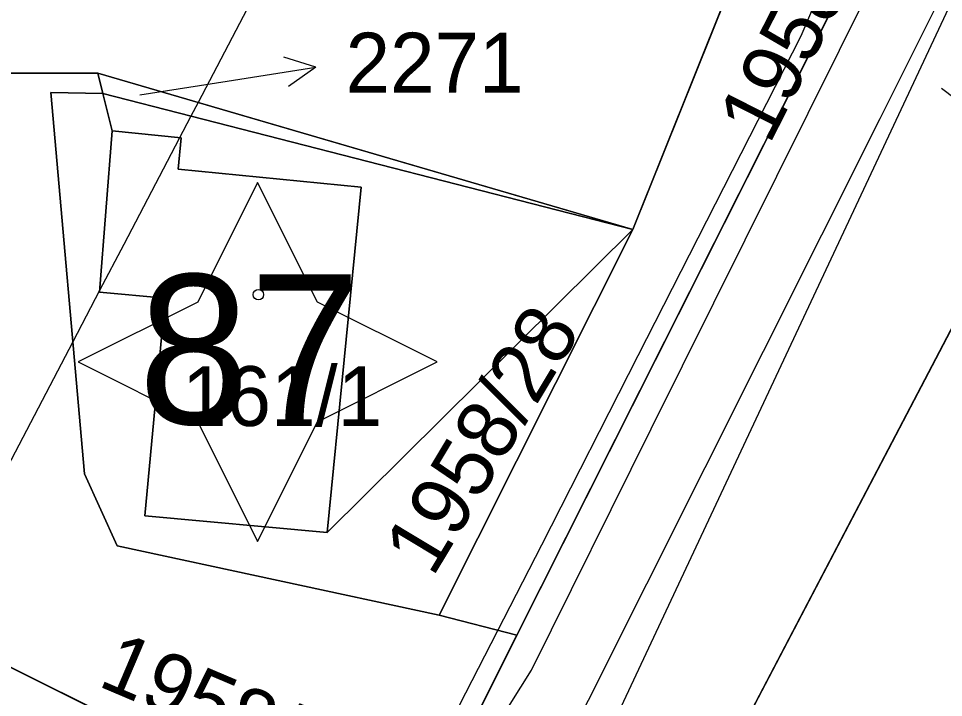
# Model space of a CAD drawing. Extents: x -706130 to -698555, y -971544 to -967260.
# Drawn here: x -704369.6 to -704338.67, y -970237.74 to -970215.04 of the extents above; entities that cross this region are included whole.
import ezdxf

# ---------------------------------------------------------------- set-up
doc = ezdxf.new("R2010")
doc.units = 0
for name, color, linetype in [('Architektonicky cenná stavba S', 7, 'Continuous'), ('BPEJ hranice S', 7, 'Continuous'), ('BPEJ I-II trida ochrany S', 7, 'Continuous'), ('Docházková izochrona - BUS S', 7, 'Continuous'), ('Docházková izochrona - VLAK N', 7, 'Continuous'), ('Kanalizace_stoka bez rozlišení N', 7, 'Continuous'), ('KN_Budovy', 7, 'Continuous'), ('KN_Budovy_cisla_domovni', 7, 'Continuous'), ('KN_Hranice_parcel', 7, 'Continuous'), ('KN_Hranice_parcel_vnitrni_kresba', 7, 'Continuous'), ('KN_Parcelni cisla', 7, 'Continuous'), ('KN_Parcelni cisla_sipky', 7, 'Continuous'), ('KN_Polygon parcely', 7, 'Continuous'), ('KN_POZEMKY_13_ZASTAVENA PLOCHA', 7, 'Continuous'), ('KN_POZEMKY_14_OSTATNI PLOCHA', 7, 'Continuous'), ('KN_POZEMKY_5_ZAHRADA', 7, 'Continuous'), ('KN_VYUZITI_16_ostatni plocha_silnice', 7, 'Continuous'), ('KN_VYUZITI_17_ostatni plocha_ostatni komunikace', 7, 'Continuous'), ('KN_VYUZITI_23_ostatni plocha_manipulacni plocha', 7, 'Continuous'), ('KN_VYUZITI_26_ostatni plocha_jina plocha', 7, 'Continuous'), ('KN_Značky budov', 7, 'Continuous'), ('Komunikace III třídy osy S', 7, 'Continuous'), ('Plochy doprava silniční - silnice III třídy S', 7, 'Continuous'), ('Plochy smíšené obytné venkovské S', 7, 'Continuous'), ('Plynovody STL S', 7, 'Continuous'), ('Regulační bloky zastavěné S', 7, 'Continuous'), ('Trasy cykloturistické N', 7, 'Continuous'), ('Vodovodní řady - rozváděcí S', 7, 'Continuous')]:
    doc.layers.add(name, color=color, linetype=linetype)

msp = doc.modelspace()

# ---------------------------------------------------------------- linework, layer by layer
at = {"layer": 'Architektonicky cenná stavba S'}
msp.add_lwpolyline([(-704361.604, -970220.52), (-704363.604, -970224.52), (-704367.604, -970226.52), (-704363.604, -970228.52), (-704361.604, -970232.52), (-704359.604, -970228.52), (-704355.604, -970226.52), (-704359.604, -970224.52)], close=True, dxfattribs=at)
at = {"layer": 'BPEJ hranice S'}
msp.add_lwpolyline([(-704355.235, -970193.101), (-704355.864, -970195.572), (-704358.07, -970204.241), (-704359.571, -970210.143), (-704363.596, -970217.84), (-704363.835, -970218.296), (-704366.078, -970222.587), (-704366.886, -970224.131), (-704367.782, -970225.844), (-704370.102, -970230.283)], dxfattribs=at)
at = {"layer": 'BPEJ I-II trida ochrany S'}
for p, q in [((-704349.06, -970222.09), (-704344.34, -970210.34)), ((-704363.596, -970217.84), (-704349.06, -970222.09)), ((-704349.06, -970222.09), (-704359.28, -970232.22)), ((-704355.53, -970234.99), (-704349.06, -970222.09)), ((-704337.45, -970223.6), (-704350.46, -970248.43)), ((-704366.89, -970224.19), (-704366.885, -970224.13)), ((-704364.7, -970224.39), (-704366.89, -970224.19)), ((-704365.37, -970231.66), (-704364.7, -970224.39)), ((-704367.781, -970225.843), (-704367.39, -970230.26)), ((-704367.39, -970230.26), (-704366.3, -970232.67)), ((-704359.28, -970232.22), (-704365.37, -970231.66)), ((-704366.3, -970232.67), (-704355.53, -970234.99))]:
    msp.add_line(p, q, dxfattribs=at)
for points in [[(-704358.07, -970204.242), (-704359.571, -970210.143), (-704363.596, -970217.84), (-704363.596, -970217.84)], [(-704366.885, -970224.13), (-704366.886, -970224.131), (-704367.781, -970225.843)]]:
    msp.add_lwpolyline(points, dxfattribs=at)
at = {"layer": 'Docházková izochrona - BUS S'}
msp.add_arc((-704361.829, -969946.93), 400, 155.51821, 17.33949, dxfattribs=at)
at = {"layer": 'Docházková izochrona - VLAK N'}
msp.add_circle((-704165.451, -969778.767), 800, dxfattribs=at)
at = {"layer": 'Kanalizace_stoka bez rozlišení N'}
for points in [[(-704315.708, -970108.899), (-704316.113, -970109.917), (-704324.867, -970134.026), (-704326.632, -970179.784), (-704337.75, -970213.085), (-704365.425, -970272.107), (-704371.374, -970294.506), (-704373.709, -970351.804), (-704376.113, -970385.719), (-704398.194, -970423.758)], [(-704338.733, -970217.369), (-704320.973, -970230.788), (-704296.056, -970253.992)]]:
    msp.add_lwpolyline(points, dxfattribs=at)
at = {"layer": 'KN_Budovy'}
msp.add_lwpolyline([(-704366.89, -970224.19), (-704364.7, -970224.39), (-704365.37, -970231.66), (-704359.28, -970232.22), (-704358.14, -970220.67), (-704364.26, -970220.07), (-704364.16, -970219.02), (-704366.47, -970218.79)], close=True, dxfattribs=at)
at = {"layer": 'KN_Hranice_parcel'}
for p, q in [((-704349.06, -970222.09), (-704344.34, -970210.34)), ((-704352.93, -970235.65), (-704340.61, -970211.17)), ((-704370.83, -970216.86), (-704366.95, -970216.86)), ((-704366.95, -970216.86), (-704349.06, -970222.09)), ((-704366.78, -970217.54), (-704366.95, -970216.86)), ((-704349.06, -970222.09), (-704366.78, -970217.54)), ((-704349.06, -970222.09), (-704355.53, -970234.99)), ((-704337.45, -970223.6), (-704350.46, -970248.43)), ((-704355.53, -970234.99), (-704352.93, -970235.65)), ((-704356.76, -970243.29), (-704352.93, -970235.65))]:
    msp.add_line(p, q, dxfattribs=at)
for points in [[(-704366.78, -970217.54), (-704368.52, -970217.51), (-704367.39, -970230.26), (-704366.3, -970232.67), (-704355.53, -970234.99)], [(-704366.78, -970217.54), (-704366.47, -970218.79), (-704366.89, -970224.19), (-704364.7, -970224.39), (-704365.37, -970231.66), (-704359.28, -970232.22), (-704349.06, -970222.09)], [(-704375.38, -970237.42), (-704372.16, -970235.59), (-704358.88, -970242.2), (-704356.76, -970243.29)]]:
    msp.add_lwpolyline(points, dxfattribs=at)
at = {"layer": 'KN_Hranice_parcel_vnitrni_kresba'}
for p, q in [((-704366.47, -970218.79), (-704364.16, -970219.02)), ((-704364.16, -970219.02), (-704364.26, -970220.07)), ((-704364.26, -970220.07), (-704358.14, -970220.67)), ((-704358.14, -970220.67), (-704359.28, -970232.22))]:
    msp.add_line(p, q, dxfattribs=at)
at = {"layer": 'KN_Parcelni cisla_sipky'}
for p, q in [((-704359.656, -970216.661), (-704360.723, -970216.323)), ((-704362.62, -970217.13), (-704359.656, -970216.661)), ((-704359.656, -970216.661), (-704360.567, -970217.312)), ((-704365.54, -970217.59), (-704362.62, -970217.13))]:
    msp.add_line(p, q, dxfattribs=at)
at = {"layer": 'KN_Polygon parcely'}
for points in [[(-704332.12, -970180.63), (-704338.7, -970204.45), (-704340.61, -970211.17), (-704352.93, -970235.65), (-704356.76, -970243.29), (-704364.41, -970258.54), (-704369.07, -970266.34), (-704369.54, -970267.12), (-704375.45, -970281.66), (-704375.62, -970282.06), (-704376.41, -970288.62)], [(-704366.65, -970284.79), (-704361.08, -970269.38), (-704350.46, -970248.43), (-704337.45, -970223.6), (-704331.07, -970212.4), (-704330.57, -970211.6), (-704328.65, -970201.47), (-704328.2, -970197.68), (-704327.21, -970194.48), (-704325.58, -970189.23)]]:
    msp.add_lwpolyline(points, dxfattribs=at)
for points in [[(-704376.32, -970216.88), (-704370.83, -970216.86), (-704366.95, -970216.86), (-704349.06, -970222.09), (-704344.34, -970210.34), (-704345.83, -970208.58), (-704346.44, -970208.42), (-704347.37, -970212.32), (-704354.63, -970210.82), (-704353.47, -970205.19), (-704358.66, -970204.12), (-704358.6, -970203.85), (-704367.89, -970204.12), (-704367.99, -970195.08), (-704373.48, -970194.98), (-704376.21, -970206.63), (-704379.9, -970214.31), (-704376.3, -970214.28)], [(-704340.61, -970211.17), (-704344.34, -970210.34), (-704349.06, -970222.09), (-704355.53, -970234.99), (-704352.93, -970235.65)], [(-704366.78, -970217.54), (-704366.95, -970216.86), (-704370.83, -970216.86), (-704371.02, -970226.09), (-704375.2, -970236.79), (-704375.38, -970237.42), (-704372.16, -970235.59), (-704358.88, -970242.2), (-704356.76, -970243.29), (-704352.93, -970235.65), (-704355.53, -970234.99), (-704366.3, -970232.67), (-704367.39, -970230.26), (-704368.52, -970217.51)], [(-704349.06, -970222.09), (-704366.95, -970216.86), (-704366.78, -970217.54)], [(-704366.78, -970217.54), (-704368.52, -970217.51), (-704367.39, -970230.26), (-704366.3, -970232.67), (-704355.53, -970234.99), (-704349.06, -970222.09), (-704359.28, -970232.22), (-704365.37, -970231.66), (-704364.7, -970224.39), (-704366.89, -970224.19), (-704366.47, -970218.79)], [(-704366.89, -970224.19), (-704364.7, -970224.39), (-704365.37, -970231.66), (-704359.28, -970232.22), (-704349.06, -970222.09), (-704366.78, -970217.54), (-704366.47, -970218.79)], [(-704348.38, -970249.44), (-704336.11, -970255.37), (-704325.34, -970227.68), (-704337.45, -970223.6), (-704350.46, -970248.43)], [(-704356.76, -970243.29), (-704358.88, -970242.2), (-704372.16, -970235.59), (-704375.38, -970237.42), (-704372.07, -970239.22), (-704367.55, -970241.44), (-704363.61, -970243.38), (-704369.66, -970255.89), (-704366.7, -970257.35), (-704364.41, -970258.54)]]:
    msp.add_lwpolyline(points, close=True, dxfattribs=at)
at = {"layer": 'KN_POZEMKY_13_ZASTAVENA PLOCHA'}
for p, q in [((-704366.47, -970218.79), (-704366.78, -970217.54)), ((-704366.78, -970217.54), (-704349.06, -970222.09)), ((-704366.89, -970224.19), (-704366.47, -970218.79)), ((-704349.06, -970222.09), (-704359.28, -970232.22)), ((-704364.7, -970224.39), (-704366.89, -970224.19)), ((-704365.37, -970231.66), (-704364.7, -970224.39)), ((-704359.28, -970232.22), (-704365.37, -970231.66))]:
    msp.add_line(p, q, dxfattribs=at)
at = {"layer": 'KN_POZEMKY_14_OSTATNI PLOCHA'}
for p, q in [((-704349.06, -970222.09), (-704344.34, -970210.34)), ((-704352.93, -970235.65), (-704340.61, -970211.17)), ((-704340.61, -970211.17), (-704352.93, -970235.65)), ((-704370.83, -970216.86), (-704366.95, -970216.86)), ((-704366.95, -970216.86), (-704366.78, -970217.54)), ((-704366.78, -970217.54), (-704366.95, -970216.86)), ((-704366.95, -970216.86), (-704349.06, -970222.09)), ((-704366.78, -970217.54), (-704368.52, -970217.51)), ((-704368.52, -970217.51), (-704367.39, -970230.26)), ((-704349.06, -970222.09), (-704366.78, -970217.54)), ((-704355.53, -970234.99), (-704349.06, -970222.09)), ((-704337.45, -970223.6), (-704350.46, -970248.43)), ((-704367.39, -970230.26), (-704366.3, -970232.67)), ((-704366.3, -970232.67), (-704355.53, -970234.99)), ((-704355.53, -970234.99), (-704352.93, -970235.65)), ((-704352.93, -970235.65), (-704355.53, -970234.99)), ((-704358.88, -970242.2), (-704372.16, -970235.59)), ((-704372.16, -970235.59), (-704358.88, -970242.2)), ((-704352.93, -970235.65), (-704356.76, -970243.29)), ((-704356.76, -970243.29), (-704352.93, -970235.65))]:
    msp.add_line(p, q, dxfattribs=at)
at = {"layer": 'KN_POZEMKY_5_ZAHRADA'}
for p, q in [((-704344.34, -970210.34), (-704349.06, -970222.09)), ((-704366.95, -970216.86), (-704370.83, -970216.86)), ((-704349.06, -970222.09), (-704366.95, -970216.86)), ((-704367.39, -970230.26), (-704368.52, -970217.51)), ((-704368.52, -970217.51), (-704366.78, -970217.54)), ((-704366.78, -970217.54), (-704366.47, -970218.79)), ((-704366.47, -970218.79), (-704366.89, -970224.19)), ((-704359.28, -970232.22), (-704349.06, -970222.09)), ((-704349.06, -970222.09), (-704355.53, -970234.99)), ((-704350.46, -970248.43), (-704337.45, -970223.6)), ((-704366.89, -970224.19), (-704364.7, -970224.39)), ((-704364.7, -970224.39), (-704365.37, -970231.66)), ((-704366.3, -970232.67), (-704367.39, -970230.26)), ((-704365.37, -970231.66), (-704359.28, -970232.22)), ((-704355.53, -970234.99), (-704366.3, -970232.67))]:
    msp.add_line(p, q, dxfattribs=at)
at = {"layer": 'KN_VYUZITI_16_ostatni plocha_silnice'}
for p, q in [((-704352.93, -970235.65), (-704340.61, -970211.17)), ((-704337.45, -970223.6), (-704350.46, -970248.43)), ((-704356.76, -970243.29), (-704352.93, -970235.65))]:
    msp.add_line(p, q, dxfattribs=at)
at = {"layer": 'KN_VYUZITI_17_ostatni plocha_ostatni komunikace'}
for p, q in [((-704349.06, -970222.09), (-704344.34, -970210.34)), ((-704340.61, -970211.17), (-704352.93, -970235.65)), ((-704355.53, -970234.99), (-704349.06, -970222.09)), ((-704352.93, -970235.65), (-704355.53, -970234.99))]:
    msp.add_line(p, q, dxfattribs=at)
at = {"layer": 'KN_VYUZITI_23_ostatni plocha_manipulacni plocha'}
for p, q in [((-704370.83, -970216.86), (-704366.95, -970216.86)), ((-704366.95, -970216.86), (-704366.78, -970217.54)), ((-704366.78, -970217.54), (-704368.52, -970217.51)), ((-704368.52, -970217.51), (-704367.39, -970230.26)), ((-704367.39, -970230.26), (-704366.3, -970232.67)), ((-704366.3, -970232.67), (-704355.53, -970234.99)), ((-704355.53, -970234.99), (-704352.93, -970235.65)), ((-704358.88, -970242.2), (-704372.16, -970235.59)), ((-704372.16, -970235.59), (-704358.88, -970242.2)), ((-704352.93, -970235.65), (-704356.76, -970243.29))]:
    msp.add_line(p, q, dxfattribs=at)
at = {"layer": 'KN_VYUZITI_26_ostatni plocha_jina plocha'}
for p, q in [((-704366.78, -970217.54), (-704366.95, -970216.86)), ((-704366.95, -970216.86), (-704349.06, -970222.09)), ((-704349.06, -970222.09), (-704366.78, -970217.54))]:
    msp.add_line(p, q, dxfattribs=at)
at = {"layer": 'KN_Značky budov'}
msp.add_circle((-704361.577, -970224.269), 0.175, dxfattribs=at)
at = {"layer": 'Komunikace III třídy osy S'}
msp.add_lwpolyline([(-704330.93, -970188.51), (-704335.437, -970204.681), (-704336.48, -970208.22), (-704338.18, -970213.14), (-704340.791, -970218.395), (-704362.238, -970261.156), (-704368.668, -970276.027), (-704371.631, -970286.925), (-704374.154, -970304.881), (-704375.815, -970349.829), (-704377.52, -970379.09), (-704378.33, -970382.9), (-704379.81, -970387.16), (-704381.8, -970391.97), (-704383.72, -970396.25), (-704386.32, -970401.18), (-704392.36, -970410.73), (-704399.98, -970422.96)], dxfattribs=at)
at = {"layer": 'Plochy doprava silniční - silnice III třídy S'}
for p, q in [((-704340.61, -970211.17), (-704352.93, -970235.65)), ((-704350.46, -970248.43), (-704337.45, -970223.6)), ((-704352.93, -970235.65), (-704356.76, -970243.29))]:
    msp.add_line(p, q, dxfattribs=at)
at = {"layer": 'Plochy smíšené obytné venkovské S'}
for p, q in [((-704352.93, -970235.65), (-704340.61, -970211.17)), ((-704337.45, -970223.6), (-704350.46, -970248.43)), ((-704356.76, -970243.29), (-704352.93, -970235.65))]:
    msp.add_line(p, q, dxfattribs=at)
at = {"layer": 'Plynovody STL S'}
msp.add_lwpolyline([(-704375.535, -970290.001), (-704372.96, -970278.67), (-704368.945, -970266.662), (-704368.62, -970265.69), (-704365.144, -970258.522), (-704361.06, -970250.1), (-704360.06, -970248.15), (-704357.178, -970242.53), (-704352.1, -970232.63), (-704348.876, -970226.302), (-704343.43, -970215.61), (-704341.145, -970210.248), (-704340.08, -970207.75), (-704336.877, -970197.883), (-704330.259, -970199.357), (-704330.25, -970199.36), (-704327.768, -970189.289)], dxfattribs=at)
at = {"layer": 'Regulační bloky zastavěné S'}
for p, q in [((-704352.93, -970235.65), (-704340.61, -970211.17)), ((-704340.61, -970211.17), (-704352.93, -970235.65)), ((-704337.45, -970223.6), (-704350.46, -970248.43)), ((-704350.46, -970248.43), (-704337.45, -970223.6)), ((-704356.76, -970243.29), (-704352.93, -970235.65)), ((-704352.93, -970235.65), (-704356.76, -970243.29))]:
    msp.add_line(p, q, dxfattribs=at)
at = {"layer": 'Trasy cykloturistické N'}
msp.add_lwpolyline([(-704397.28, -970427.29), (-704386.46, -970409.76), (-704381.94, -970403.15), (-704375.12, -970393.19), (-704372.65, -970386.41), (-704370.59, -970346.53), (-704369.52, -970316.88), (-704368.75, -970300.09), (-704366.65, -970284.79), (-704361.08, -970269.38), (-704350.46, -970248.43), (-704337.45, -970223.6), (-704330.57, -970211.6), (-704328.2, -970197.68), (-704324.27, -970184.8)], dxfattribs=at)
at = {"layer": 'Vodovodní řady - rozváděcí S'}
msp.add_lwpolyline([(-704370.399, -970278.264), (-704368.59, -970272.36), (-704365.51, -970264.7), (-704360.14, -970251.79), (-704354.28, -970239.76), (-704352.44, -970236.83), (-704348.44, -970228.75), (-704341.09, -970213.98)], dxfattribs=at)

# ---------------------------------------------------------------- texts
at = {"layer": 'KN_Budovy_cisla_domovni'}
msp.add_text('87', height=5, dxfattribs=at).set_placement((-704365.593, -970228.594))
at = {"layer": 'KN_Parcelni cisla'}
for s, rotation, p in [('1958/3', 63, (-704344.492, -970219.285)), ('1958/28', 59, (-704355.751, -970233.753)), ('1958/34', 337, (-704366.992, -970237.332))]:
    msp.add_text(s, height=2, rotation=rotation, dxfattribs=at).set_placement(p)
for s, p in [('2271', (-704358.66, -970217.51)), ('161/1', (-704364.13, -970228.66))]:
    msp.add_text(s, height=2, dxfattribs=at).set_placement(p)

doc.saveas('drawing.dxf')
